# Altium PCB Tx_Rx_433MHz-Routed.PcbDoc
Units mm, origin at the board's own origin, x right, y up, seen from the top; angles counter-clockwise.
Board outline 100 x 100 mm, 4 copper layers (SIGNAL_1, SIGNAL_2, SIGNAL_3, SIGNAL_4), stack 1.58 mm thick; 85 components, 84 nets, 318 pads, 423 vias.
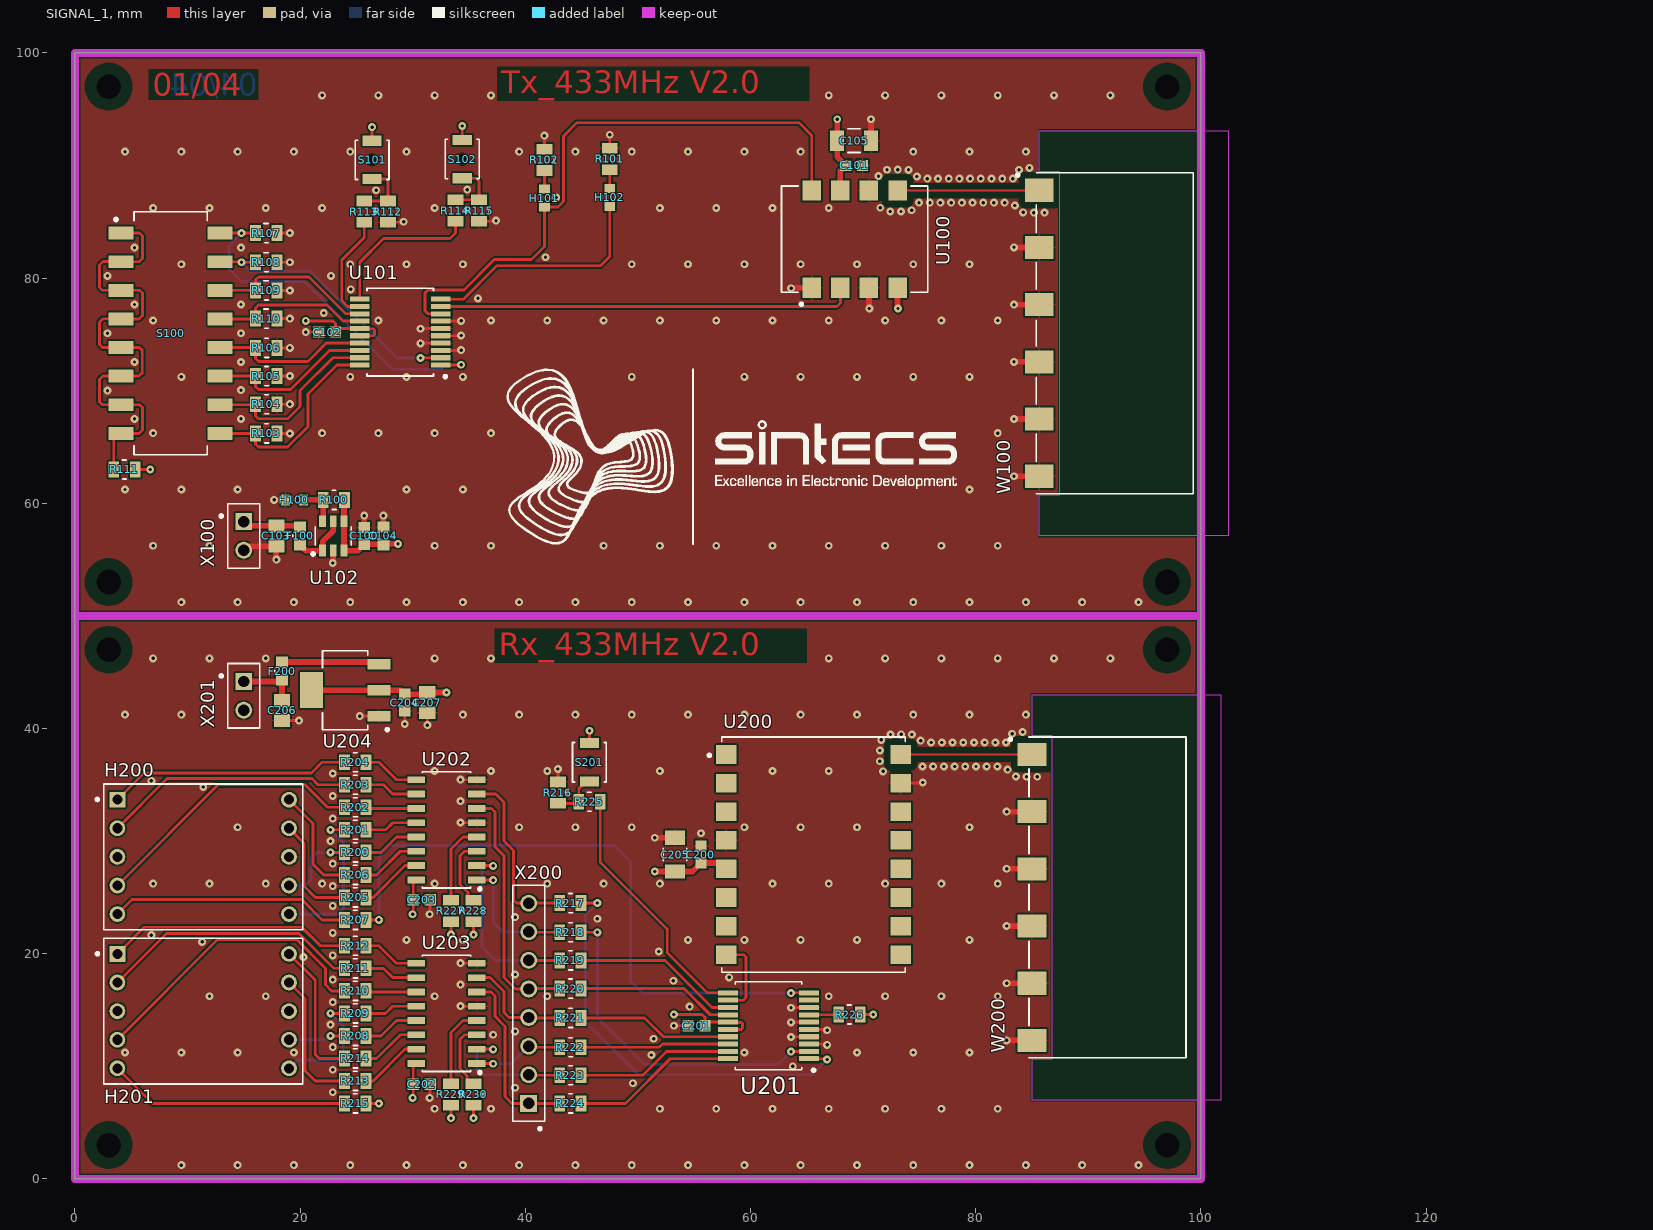
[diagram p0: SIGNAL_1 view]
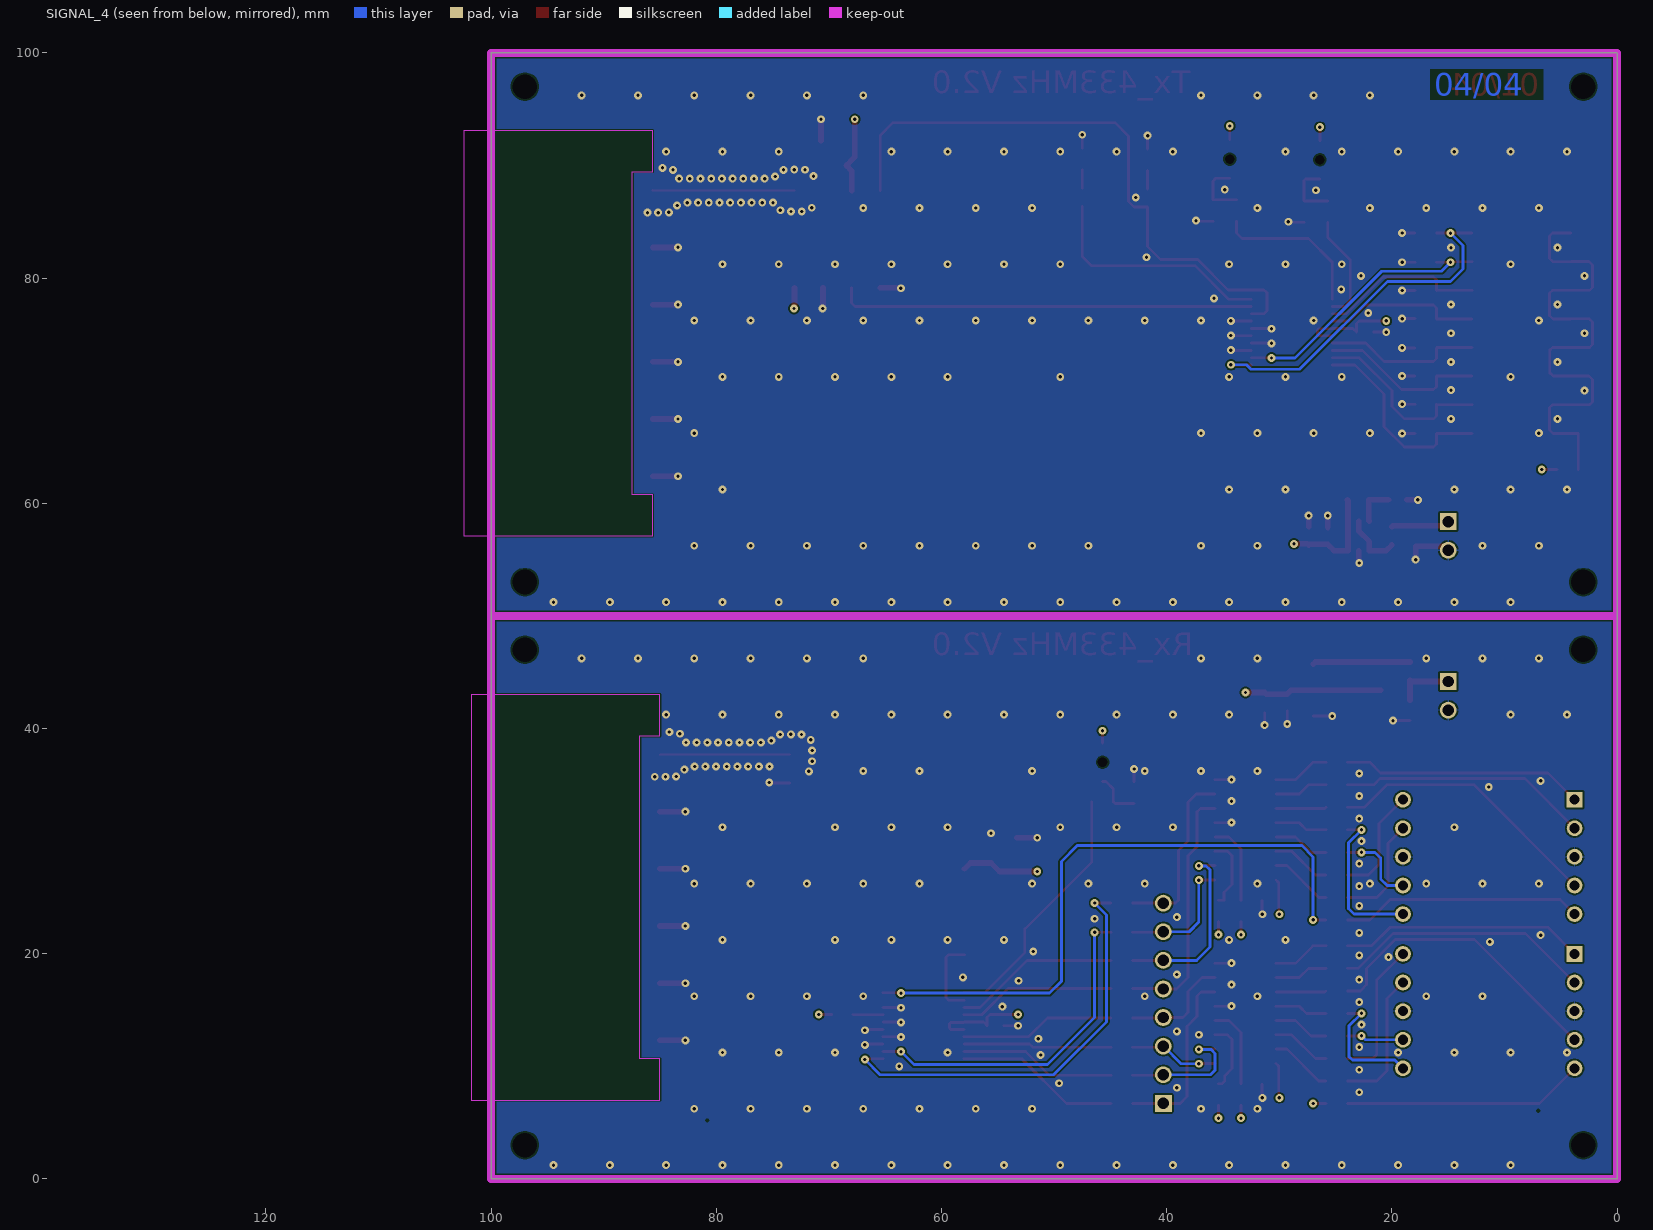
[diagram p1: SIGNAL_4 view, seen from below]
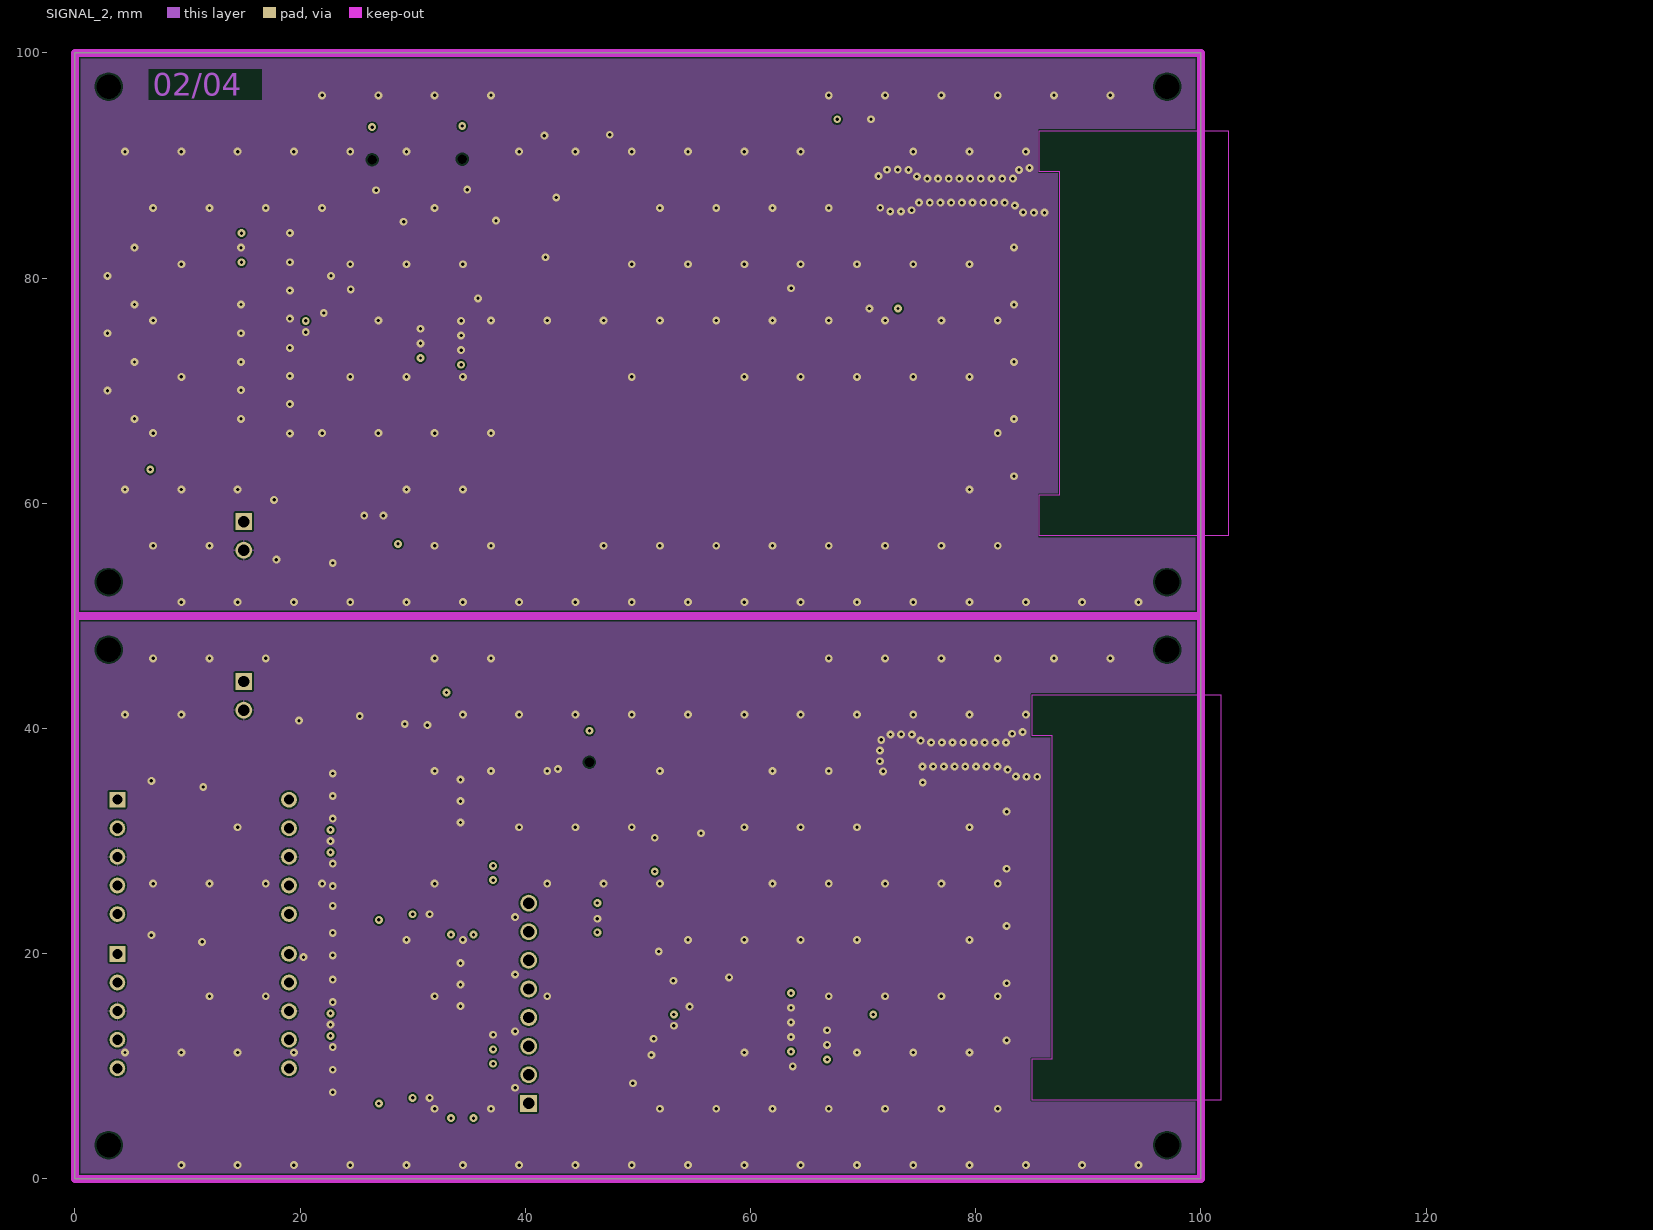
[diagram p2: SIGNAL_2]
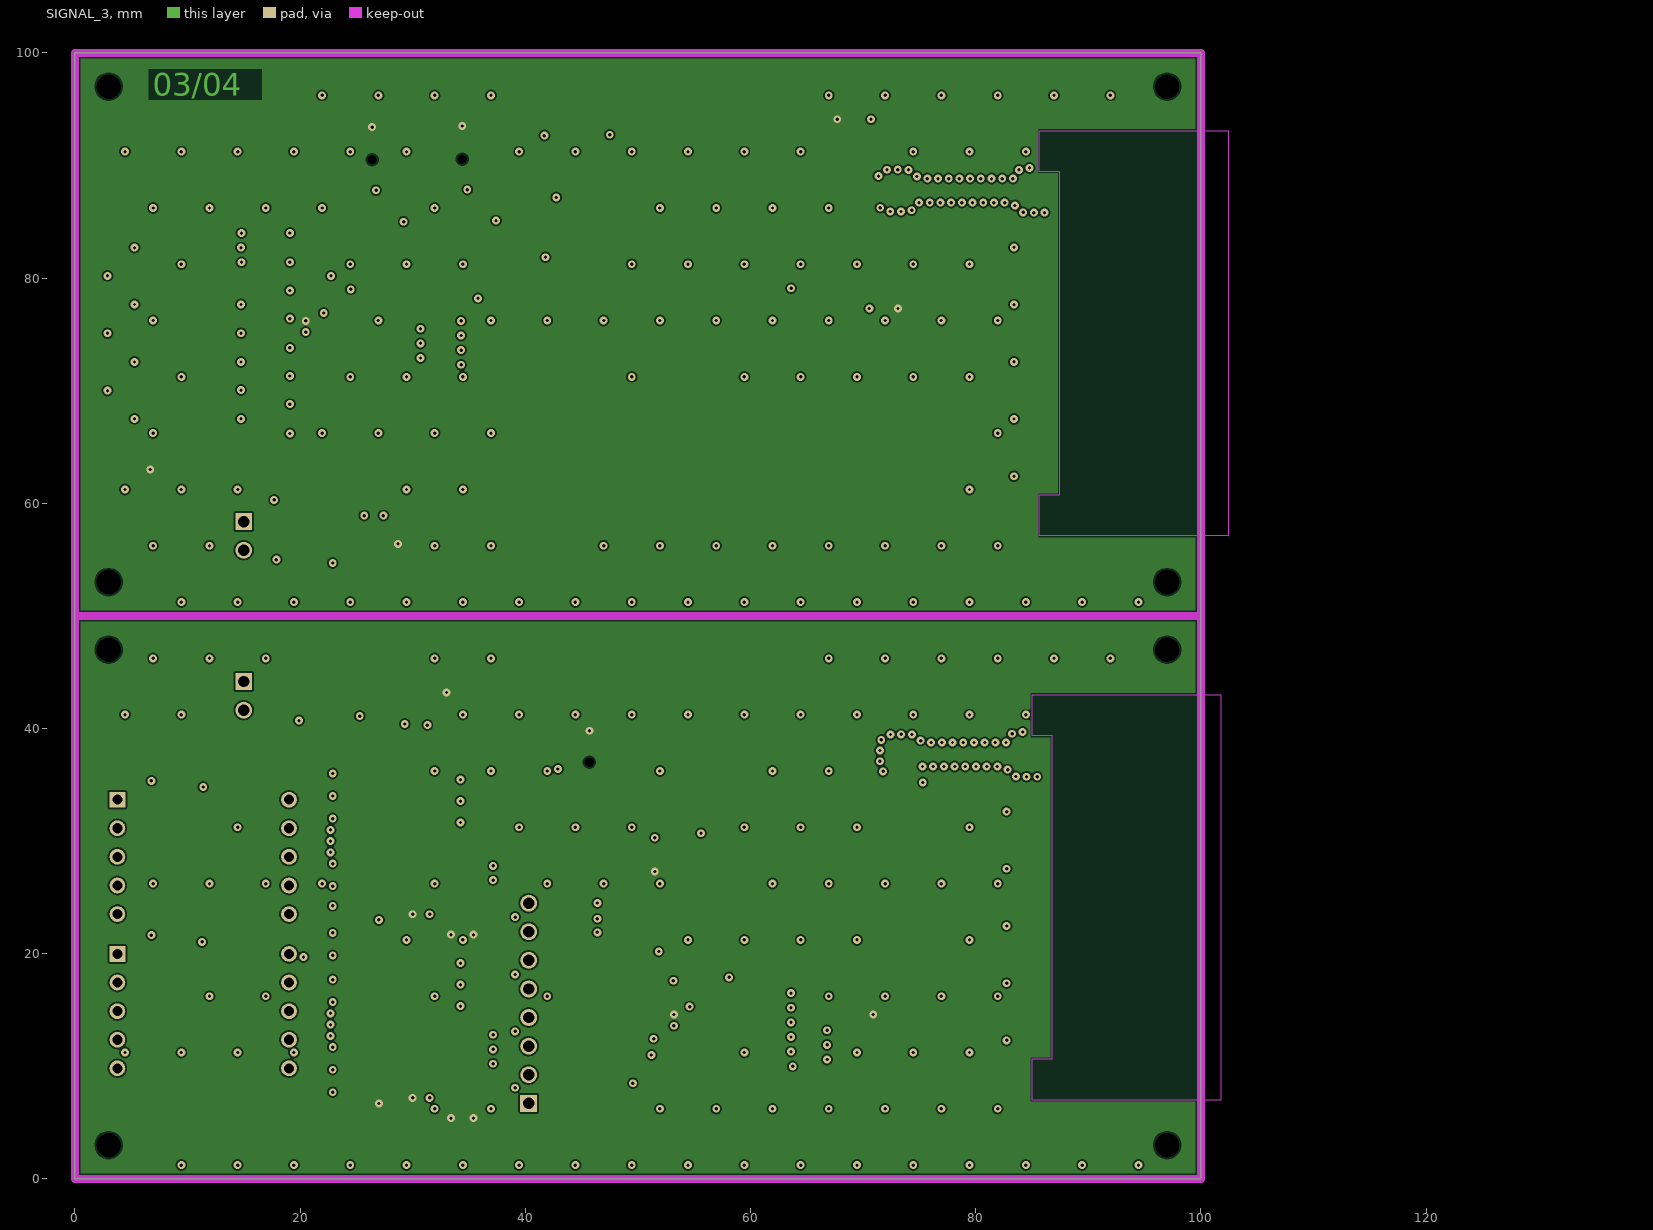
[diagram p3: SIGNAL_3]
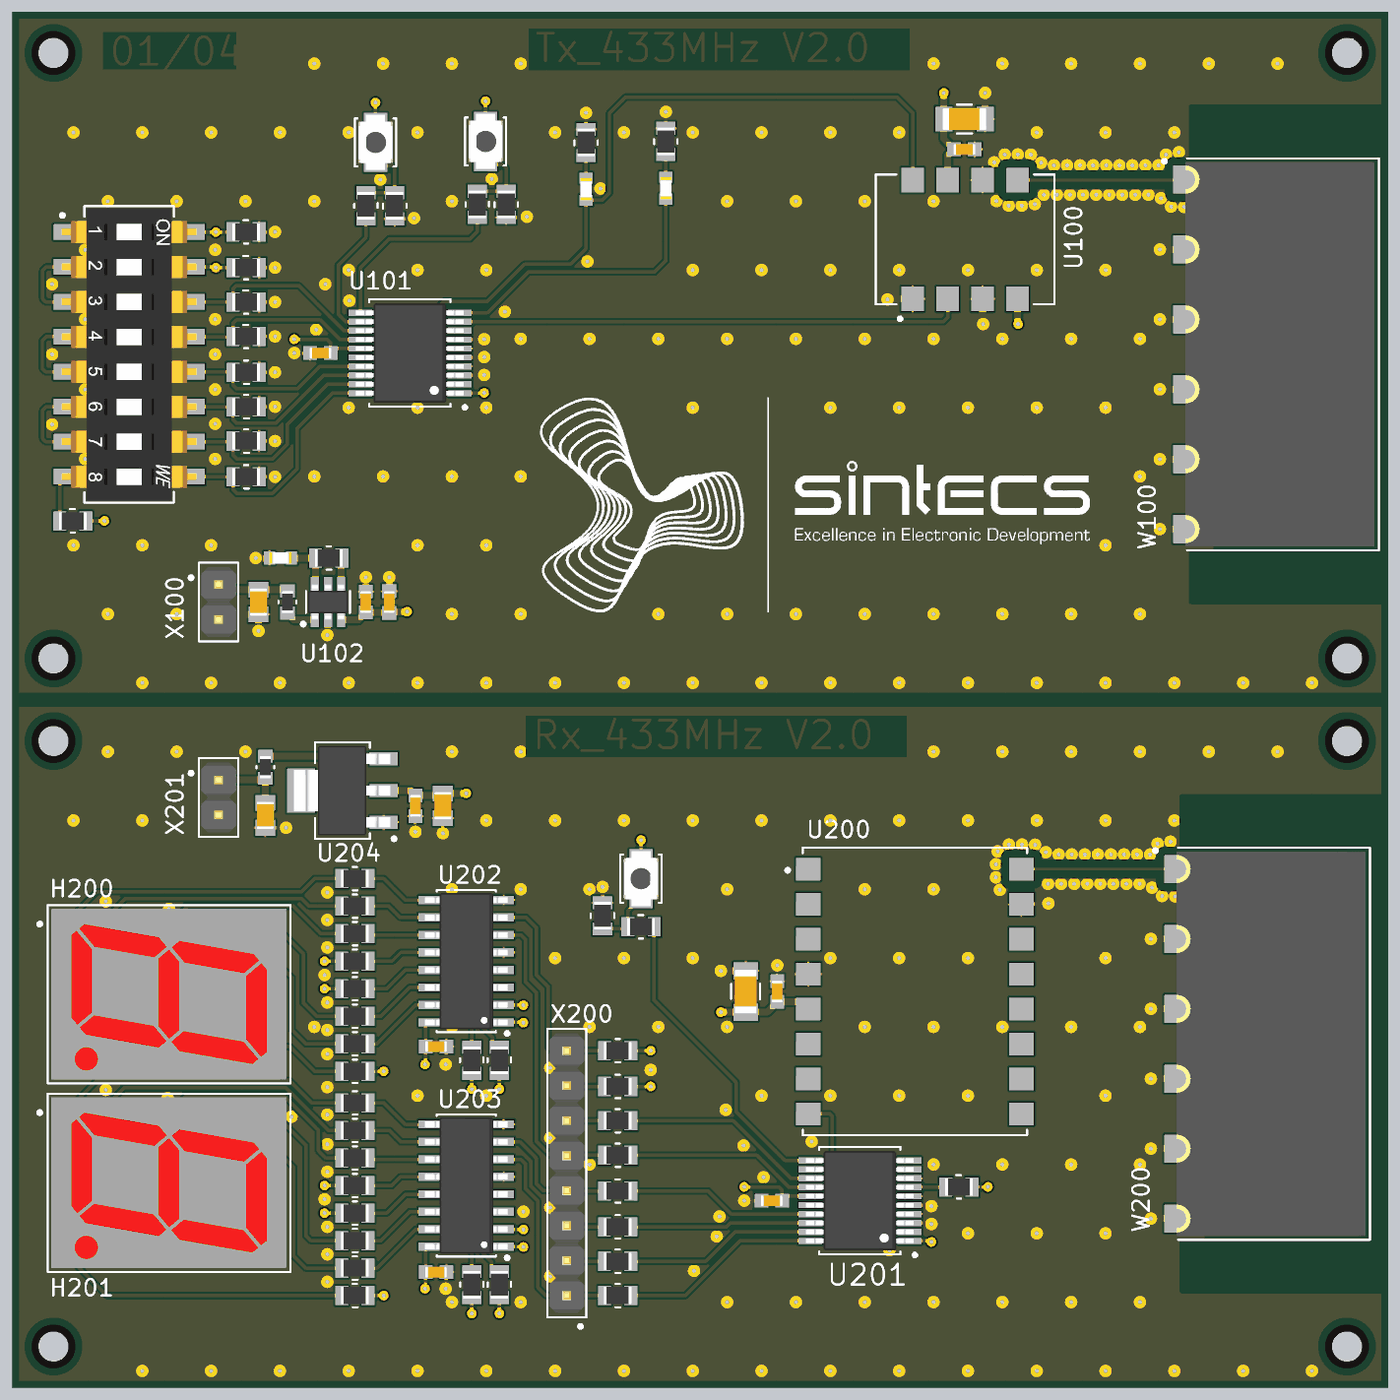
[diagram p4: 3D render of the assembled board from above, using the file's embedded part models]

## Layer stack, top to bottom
DIELECTRIC_1: solder mask 0.01, Dk 1
SIGNAL_1: signal copper 0.035
DIELECTRIC_3: prepreg 0.12, Dk 4.7
SIGNAL_2: signal copper 0.035
DIELECTRIC_5: prepreg 1.2, Dk 4.7
SIGNAL_3: signal copper 0.035
DIELECTRIC_7: prepreg 0.12, Dk 4.7
SIGNAL_4: signal copper 0.035
DIELECTRIC_9: solder mask 0.01, Dk 1

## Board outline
0,0 100,0 100,100 0,100

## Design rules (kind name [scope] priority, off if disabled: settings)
Clearance Clearance_50R [InNetClass('50R') vs Not Keepout] p1: gap=0.6 ignorepadtopadclearanceinfootprint=FALSE except(0.2: SMDPad-SMDPad)
Clearance [All] p2: gap=0.15 ignorepadtopadclearanceinfootprint=FALSE
ComponentClearance [All] p1: gap=0.1 collisioncheckmode=3 verticalgap=0.254 showdistances=FALSE
DiffPairsRouting [All] p1: maxlimit=0.254 minlimit=0.254 mostfreqgap=0.254 toplayer_minwidth=0.15 toplayer_maxwidth=0.3 toplayer_prefwidth=0.15 midlayer1_minwidth=0.15 midlayer1_maxwidth=0.3 midlayer1_prefwidth=0.15 midlayer2_minwidth=0.15 midlayer2_maxwidth=0.3 midlayer2_prefwidth=0.15 bottomlayer_minwidth=0.15 bottomlayer_maxwidth=0.3 bottomlayer_prefwidth=0.15 maxuncoupledlength=12.7
MinimumSolderMaskSliver [All] p1: minsoldermaskwidth=0.1
PolygonConnect [All] p1: thpad.connectstyle=Relief thpad.reliefconductorwidth=0.15 thpad.reliefentries=4 thpad.polygonreliefangle="90 Angle" thpad.airgapwidth=0.15 smdpad.connectstyle=Relief smdpad.reliefconductorwidth=0.15 smdpad.reliefentries=4 smdpad.polygonreliefangle="90 Angle" smdpad.airgapwidth=0.15 via.connectstyle=Direct via.reliefconductorwidth=0.127 via.reliefentries=2 via.polygonreliefangle="90 Angle" via.airgapwidth=0.152
RoutingVias [All] p1: holewidth=0.3 width=0.7 viastyle="Through Hole" minholewidth=0.3 minwidth=0.7 maxholewidth=0.3 maxwidth=0.7
SilkToSilkClearance [All] p1: silktosilkclearance=0.1
SolderMaskExpansion SolderMaskExpansion_Via [IsVia] p1: expansion=0.075 istentingtop=FALSE soldermaskfromhole=TRUE
SolderMaskExpansion [All] p2: expansion=0.1 istentingtop=FALSE
UnRoutedNet [All] p1: checkbadconnections=TRUE
Width "Width for 50E_SE" [InNetClass('50R')] p1: maxlimit=0.2 minlimit=0.185 preferedwidth=0.2 toplayer_minwidth=0.2 bottomlayer_minwidth=0.2 impedanceprofiledriven=TRUE impedanceprofileid={877E34D1-77DC-4DEE-A0FB-207FE4FBDA97} impedanceprofilevalue=50.000000 minimp=50.000000 maximp=50.000000 favimp=50.000000
Width [All] p2: maxlimit=1 minlimit=0.15 preferedwidth=0.2
25 further rules are at their usual default settings.

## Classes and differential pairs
net class 50R: RF_RX RF_TX
component class TX: C100 C101 C102 C103 C104 C105 F100 H100 H101 H102 R100 R101 R102 R103 R104 R105 R106 R107 R108 R109 R110 R111 R112 R113 R114 R115 S100 S101 S102 U100 U101 U102 W100 X100
component class RX: C200 C201 C202 C203 C204 C205 C206 C207 F200 H200 H201 R200 R201 R202 R203 R204 R205 R206 R207 R208 R209 R210 R211 R212 R213 R214 R215 R216 R217 R218 R219 R220 R221 R222 R223 R224 R225 R226 R227 R228 R229 R230 S201 U200 U201 U202 U203 U204 W200 X200 X201
polygon class "\"(Inherited)\"": GND_RX_L02_P002

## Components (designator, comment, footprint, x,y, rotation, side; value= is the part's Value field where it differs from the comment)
C100 "C_0603_1608X90_GENERIC" CAPC1608X90N_0603_GENERIC 25.7,57.1 r90 top value=100nF
C101 "C_0603_1608X90_GENERIC" CAPC1608X90N_0603_GENERIC 69.2,90 r0 top value=100nF
C102 "C_0603_1608X90_GENERIC" CAPC1608X90N_0603_GENERIC 22.4,75.2 r180 top value=100nF
C103 "C_0805_2012X150_GENERIC" CAPC2012X150N_0805_GENERIC 17.9,57.1 r270 top value=1uF
C104 "CL10A226MP8NUNE" CAPC1608X105N 27.4,57.1 r90 top value=4.7uF
C105 "C_1206_3216X190_GENERIC" CAPC3216X190N_1206_GENERIC 69.2,92.2 r0 top value=10uF
C200 "C_0603_1608X90_GENERIC" CAPC1608X90N_0603_GENERIC 55.6,28.8 r90 top value=100nF
C201 "C_0603_1608X90_GENERIC" CAPC1608X90N_0603_GENERIC 55.2,13.6 r180 top value=100nF
C202 "C_0603_1608X90_GENERIC" CAPC1608X90N_0603_GENERIC 30.8,8.4 r0 top value=100nF
C203 "C_0603_1608X90_GENERIC" CAPC1608X90N_0603_GENERIC 30.8,24.8 r0 top value=100nF
C204 "C_0603_1608X90_GENERIC" CAPC1608X90N_0603_GENERIC 29.3,42.3 r270 top value=100nF
C205 "C_1206_3216X190_GENERIC" CAPC3216X190N_1206_GENERIC 53.3,28.8 r90 top value=10uF
C206 "08051C104KAZ2A" CAPC2013X140N_AVX 18.398,41.6 r270 top value=10uF
C207 "08051C104KAZ2A" CAPC2013X140N_AVX 31.3,42.3 r270 top value=10uF
F100 "0467XXXX" RESC1608X60N_0603_GENERIC 20,57.1 r270 top value=500mA
F200 "0467XXXX" RESC1608X60N_0603_GENERIC 18.4,45.1 r90 top value=500mA
H100 "KP-1608SGC" LEDC1608X110N 19.5,60.3 r180 top
H101 "KP-1608SGC" LEDC1608X110N 41.7,87.1 r90 top
H102 "KP-1608SGC" LEDC1608X110N 47.5,87.175 r90 top
H200 "HDSP-5XXX" BROADCOM_HDSP-5XXX 11.4,28.6 r0 top
H201 "HDSP-5XXX" BROADCOM_HDSP-5XXX 11.4,14.9 r0 top
R100 "R_0805_2012X60_GENERIC" RESC2012X60N_0805_GENERIC 23,60.3 r180 top value=120R
R101 "R_0805_2012X60_GENERIC" RESC2012X60N_0805_GENERIC 47.5,90.575 r90 top value=120R
R102 "R_0805_2012X60_GENERIC" RESC2012X60N_0805_GENERIC 41.7,90.5 r90 top value=120R
R103 "R_0805_2012X60_GENERIC" RESC2012X60N_0805_GENERIC 17,66.2 r180 top value=100K
R104 "R_0805_2012X60_GENERIC" RESC2012X60N_0805_GENERIC 17,68.8 r180 top value=100K
R105 "R_0805_2012X60_GENERIC" RESC2012X60N_0805_GENERIC 17,71.3 r180 top value=100K
R106 "R_0805_2012X60_GENERIC" RESC2012X60N_0805_GENERIC 17,73.8 r180 top value=100K
R107 "R_0805_2012X60_GENERIC" RESC2012X60N_0805_GENERIC 17,84 r0 top value=100K
R108 "R_0805_2012X60_GENERIC" RESC2012X60N_0805_GENERIC 17,81.4 r0 top value=100K
R109 "R_0805_2012X60_GENERIC" RESC2012X60N_0805_GENERIC 17,78.9 r0 top value=100K
R110 "R_0805_2012X60_GENERIC" RESC2012X60N_0805_GENERIC 17,76.4 r0 top value=100K
R111 "R_0805_2012X60_GENERIC" RESC2012X60N_0805_GENERIC 4.4,63 r0 top value=1K
R112 "R_0805_2012X60_GENERIC" RESC2012X60N_0805_GENERIC 27.8,85.9 r90 top value=100K
R113 "R_0805_2012X60_GENERIC" RESC2012X60N_0805_GENERIC 25.7,85.9 r270 top value=1K
R114 "R_0805_2012X60_GENERIC" RESC2012X60N_0805_GENERIC 33.8,86 r270 top value=1K
R115 "R_0805_2012X60_GENERIC" RESC2012X60N_0805_GENERIC 35.9,86 r90 top value=100K
R200 "R_0805_2012X60_GENERIC" RESC2012X60N_0805_GENERIC 24.9,29.001 r180 top value=120R
R201 "R_0805_2012X60_GENERIC" RESC2012X60N_0805_GENERIC 24.9,31.001 r180 top value=120R
R202 "R_0805_2012X60_GENERIC" RESC2012X60N_0805_GENERIC 24.9,33.001 r180 top value=120R
R203 "R_0805_2012X60_GENERIC" RESC2012X60N_0805_GENERIC 24.9,35.001 r180 top value=120R
R204 "R_0805_2012X60_GENERIC" RESC2012X60N_0805_GENERIC 24.9,37.002 r180 top value=120R
R205 "R_0805_2012X60_GENERIC" RESC2012X60N_0805_GENERIC 24.9,25 r180 top value=120R
R206 "R_0805_2012X60_GENERIC" RESC2012X60N_0805_GENERIC 24.9,27 r180 top value=120R
R207 "R_0805_2012X60_GENERIC" RESC2012X60N_0805_GENERIC 24.9,23 r180 top value=120R
R208 "R_0805_2012X60_GENERIC" RESC2012X60N_0805_GENERIC 24.9,12.7 r180 top value=120R
R209 "R_0805_2012X60_GENERIC" RESC2012X60N_0805_GENERIC 24.9,14.7 r180 top value=120R
R210 "R_0805_2012X60_GENERIC" RESC2012X60N_0805_GENERIC 24.9,16.701 r180 top value=120R
R211 "R_0805_2012X60_GENERIC" RESC2012X60N_0805_GENERIC 24.9,18.701 r180 top value=120R
R212 "R_0805_2012X60_GENERIC" RESC2012X60N_0805_GENERIC 24.9,20.701 r180 top value=120R
R213 "R_0805_2012X60_GENERIC" RESC2012X60N_0805_GENERIC 24.9,8.7 r180 top value=120R
R214 "R_0805_2012X60_GENERIC" RESC2012X60N_0805_GENERIC 24.9,10.7 r180 top value=120R
R215 "R_0805_2012X60_GENERIC" RESC2012X60N_0805_GENERIC 24.9,6.7 r180 top value=120R
R216 "R_0805_2012X60_GENERIC" RESC2012X60N_0805_GENERIC 42.9,34.3 r270 top value=100K
R217 "R_0805_2012X60_GENERIC" RESC2012X60N_0805_GENERIC 44,24.5 r180 top value=1K
R218 "R_0805_2012X60_GENERIC" RESC2012X60N_0805_GENERIC 44,21.9 r180 top value=1K
R219 "R_0805_2012X60_GENERIC" RESC2012X60N_0805_GENERIC 44,19.4 r180 top value=1K
R220 "R_0805_2012X60_GENERIC" RESC2012X60N_0805_GENERIC 44,16.9 r180 top value=1K
R221 "R_0805_2012X60_GENERIC" RESC2012X60N_0805_GENERIC 44,14.3 r180 top value=1K
R222 "R_0805_2012X60_GENERIC" RESC2012X60N_0805_GENERIC 44,11.7 r180 top value=1K
R223 "R_0805_2012X60_GENERIC" RESC2012X60N_0805_GENERIC 44,9.2 r180 top value=1K
R224 "R_0805_2012X60_GENERIC" RESC2012X60N_0805_GENERIC 44,6.7 r180 top value=1K
R225 "R_0805_2012X60_GENERIC" RESC2012X60N_0805_GENERIC 45.7,33.5 r0 top value=1K
R226 "R_0805_2012X60_GENERIC" RESC2012X60N_0805_GENERIC 68.8,14.6 r0 top value=100K
R227 "R_0805_2012X60_GENERIC" RESC2012X60N_0805_GENERIC 33.4,23.8 r270 top value=100K
R228 "R_0805_2012X60_GENERIC" RESC2012X60N_0805_GENERIC 35.4,23.8 r270 top value=100K
R229 "R_0805_2012X60_GENERIC" RESC2012X60N_0805_GENERIC 33.4,7.5 r270 top value=100K
R230 "R_0805_2012X60_GENERIC" RESC2012X60N_0805_GENERIC 35.4,7.5 r270 top value=100K
S100 "418121270808" WE_418121270808 8.5,75.1 r0 top
S101 "B3U_1000P_B" OMRON_B3U_1000P_B 26.4,90.5 r90 top
S102 "B3U_1000P_B" OMRON_B3U_1000P_B 34.402,90.57 r90 top
S201 "B3U_1000P_B" OMRON_B3U_1000P_B 45.7,37 r270 top
U100 "TXM-433-LR" LINX_TXM-433-LR 69.25,83.45 r90 top
U101 "LICAL-ENC-MS001" SOP65P780X200-20N 28.9,75.2 r180 top
U102 "MAX8881EU" SOT95P280X100-6N 22.95,57.1 r90 top
U200 "RXM-433-LR" LINX_RXM-433-LR 65.6,28.8 r0 top
U201 "LICAL-DEC-MS001" SOP65P780X200-20N 61.6,13.6 r180 top
U202 "CD74HC4511M" SOIC127P600X175-16N 33,31 r180 top
U203 "CD74HC4511M" SOIC127P600X175-16N 33,14.7 r180 top
U204 "LM1117MPX" SOT230P700X180-4N 25.498,43.4 r180 top
W100 "ANT-433-SP" LINX_ANT-433-SP 85.65,75.1 r270 top
W200 "ANT-433-SP" LINX_ANT-433-SP 85,25 r270 top
X100 "M20_9770242" HARWIN_M20_9770242 15,57.1 r270 top
X200 "M20_9770842" HARWIN_M20_9770842 40.3,15.6 r90 top
X201 "M20_9770242" HARWIN_M20_9770242 15,42.9 r270 top

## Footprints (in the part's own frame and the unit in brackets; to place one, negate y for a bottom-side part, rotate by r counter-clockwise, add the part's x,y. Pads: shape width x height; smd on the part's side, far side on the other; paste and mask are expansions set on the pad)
BROADCOM_HDSP-5XXX [mm]
  rrect1% 1.4x1.4 hole 0.9 paste-2539.97 mask-0.713: 1(-7.62,5.08)
  round 1.4 hole 0.9 paste-2539.97 mask-0.713: 2(-7.62,2.54) 3(-7.62,0) 4(-7.62,-2.54) 5(-7.62,-5.08) 6(7.62,-5.08) 7(7.62,-2.54) 8(7.62,0) 9(7.62,2.54) 10(7.62,5.08)
  silkscreen extent -9.53,-6.47 8.83,6.48, body extent -8.55,-6.2 8.55,6.2, height 8
CAPC1608X90N_0603_GENERIC [mm]
  rrect1% 1x1 smd paste+0 mask-0.513: 1(-0.75,0) 2(0.75,0)
  body extent -0.8,-0.4 0.8,0.4, height 0.8
CAPC1608X105N [mm]
  rrect1% 1x1.05 smd paste+0 mask-0.538: 1(-0.8,0) 2(0.8,0)
  body extent -0.8,-0.4 0.8,0.4, height 0.8
CAPC2012X150N_0805_GENERIC [mm]
  rrect1% 1.15x1.45 smd paste+0 mask-0.738: 1(-0.9,0) 2(0.9,0)
  body extent -1,-0.63 1,0.63, height 1
CAPC2013X140N_AVX [mm]
  rrect1% 1.15x1.45 smd paste+0 mask-0.738: 1(-0.9,0) 2(0.9,0)
  body extent -1,-0.63 1,0.63, height 1
CAPC3216X190N_1206_GENERIC [mm]
  rrect1% 1.25x1.8 smd paste+0 mask-0.913: 1(-1.5,0) 2(1.5,0)
  silkscreen extent -0.55,-1.05 0.55,1.05, body extent -1.6,-0.8 1.6,0.8, height 1.2
HARWIN_M20_9770242 [mm]
  rrect1% 1.5x1.5 hole 1 paste-2539.97 mask-0.763: 1(-1.27,0)
  round 1.5 hole 1 paste-2539.97 mask-0.763: 2(1.27,0)
  silkscreen extent -2.87,-2.13 2.86,1.42, body extent -2.54,-1.27 2.54,1.27, height 8.34
HARWIN_M20_9770842 [mm]
  rrect1% 1.5x1.5 hole 1 paste-2539.97 mask-0.763: 1(-8.89,0)
  round 1.5 hole 1 paste-2539.97 mask-0.763: 2(-6.35,0) 3(-3.81,0) 4(-1.27,0) 5(1.27,0) 6(3.81,0) 7(6.35,0) 8(8.89,0)
  silkscreen extent -11.26,-1.42 10.48,1.42, body extent -10.16,-1.27 10.16,1.27, height 8.34
LEDC1608X110N [mm]
  rrect1% 0.8x0.95 smd paste+0 mask-0.488: 1(-0.8,0) 2(0.8,0)
  body extent -0.8,-0.4 0.81,0.4, height 0.75
LINX_ANT-433-SP [mm]
  rrect1% 2.05x2.55 smd paste+0 mask-1.288: 1(-12.7,0) 2(-7.62,0) 3(-2.54,0) 4(2.54,0) 5(7.62,0) 6(12.7,0)
  Keep-Out Layer region: 14.35,0 14.35,1.8 -14.35,1.8 -14.35,0 -18,0 -18,16.78 18,16.78 18,0
  silkscreen extent -14.24,-2.04 14.24,13.67, body extent -13.97,-0.38 13.97,13.34, height 1.52
LINX_RXM-433-LR [mm]
  rrect1% 1.8x1.65 smd paste+0 mask-0.913: 1(-7.747,8.89) 2(-7.747,6.35) 3(-7.747,3.81) 4(-7.747,1.27) 5(-7.747,-1.27) 6(-7.747,-3.81) 7(-7.747,-6.35) 8(-7.747,-8.89) 9(7.747,-8.89) 10(7.747,-6.35) 11(7.747,-3.81) 12(7.747,-1.27) 13(7.747,1.27) 14(7.747,3.81) 15(7.747,6.35) 16(7.747,8.89)
  silkscreen extent -9.38,-10.45 8.15,10.45, body extent -8,-10.3 8,10.4, height 3.3
LINX_TXM-433-LR [mm]
  rrect1% 1.8x1.65 smd paste+0 mask-0.913: 1(-4.318,3.81) 2(-4.318,1.27) 3(-4.318,-1.27) 4(-4.318,-3.81) 5(4.318,-3.81) 6(4.318,-1.27) 7(4.318,1.27) 8(4.318,3.81)
  silkscreen extent -5.89,-6.5 4.72,6.5, body extent -4.6,-6.4 4.6,6.4, height 3.3
OMRON_B3U_1000P_B [mm]
  rrect1% 0.9x1.7 smd paste+0 mask-0.863: 1(-1.7,0) 2(1.7,0)
  round 0 hole 0.85 unplated paste-2539.97: ""(0,0)
  silkscreen extent -1.75,-1.5 1.75,1.5, body extent -2,-1.25 2,1.25, height 1.75
RESC1608X60N_0603_GENERIC [mm]
  rrect1% 0.95x1.05 smd paste+0 mask-0.538: 1(-0.8,0) 2(0.8,0)
  silkscreen extent -0.08,-0.65 0.08,0.65, body extent -0.8,-0.4 0.8,0.4, height 0.5
RESC2012X60N_0805_GENERIC [mm]
  rrect1% 0.95x1.4 smd paste+0 mask-0.713: 1(-0.95,0) 2(0.95,0)
  silkscreen extent -0.2,-0.85 0.15,0.85, body extent -1,-0.63 1,0.63, height 0.5
SOIC127P600X175-16N [mm]
  rrect1% 1.55x0.6 smd paste+0 mask-0.788: 1(-2.7,4.445) 2(-2.7,3.175) 3(-2.7,1.905) 4(-2.7,0.635) 5(-2.7,-0.635) 6(-2.7,-1.905) 7(-2.7,-3.175) 8(-2.7,-4.445) 9(2.7,-4.445) 10(2.7,-3.175) 11(2.7,-1.905) 12(2.7,-0.635) 13(2.7,0.635) 14(2.7,1.905) 15(2.7,3.175) 16(2.7,4.445)
  silkscreen extent -3.1,-5.16 2.15,5.38, body extent -3,-4.95 3,4.95, height 1.75
SOP65P780X200-20N [mm]
  rrect1% 1.75x0.45 smd paste+0 mask-0.888: 1(-3.6,2.925) 2(-3.6,2.275) 3(-3.6,1.625) 4(-3.6,0.975) 5(-3.6,0.325) 6(-3.6,-0.325) 7(-3.6,-0.975) 8(-3.6,-1.625) 9(-3.6,-2.275) 10(-3.6,-2.925) 11(3.6,-2.925) 12(3.6,-2.275) 13(3.6,-1.625) 14(3.6,-0.975) 15(3.6,-0.325) 16(3.6,0.325) 17(3.6,0.975) 18(3.6,1.625) 19(3.6,2.275) 20(3.6,2.925)
  silkscreen extent -4.13,-3.9 2.95,4.08, body extent -3.93,-3.6 3.93,3.6, height 2
SOT95P280X100-6N [mm]
  rrect1% 1.05x0.6 smd paste+0 mask-0.538: 1(-1.3,0.95) 2(-1.3,0) 3(-1.3,-0.95) 4(1.3,-0.95) 5(1.3,0) 6(1.3,0.95)
  silkscreen extent -1.73,-1.6 0.8,1.92, body extent -1.28,-1.45 1.28,1.45, height 1.45
SOT230P700X180-4N [mm]
  rrect1% 2.05x0.95 smd paste+0 mask-1.038: 1(-1.5,2.3) 2(-1.5,0) 3(-1.5,-2.3)
  rrect1% 2.05x3.2 smd paste+0 mask-1.613: 4(4.5,0)
  silkscreen extent -2.37,-3.5 3.5,3.63, body extent -1.98,-3.25 5.02,3.25, height 1.8
WE_418121270808 [mm]
  rrect1% 2.2x1.15 smd paste+0 mask-1.113: 1(-4.4,8.89) 2(-4.4,6.35) 3(-4.4,3.81) 4(-4.4,1.27) 5(-4.4,-1.27) 6(-4.4,-3.81) 7(-4.4,-6.35) 8(-4.4,-8.89) 9(4.4,-8.89) 10(4.4,-6.35) 11(4.4,-3.81) 12(4.4,-1.27) 13(4.4,1.27) 14(4.4,3.81) 15(4.4,6.35) 16(4.4,8.89)
  silkscreen extent -4.97,-10.78 3.25,10.78, body extent -4.9,-10.63 4.9,10.63, height 4.32

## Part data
C100 C101 C102 C200 C201 C202 C203 C204: "100nF 25V 10%", Capacitance=100000, Dielectric=X7R, Manufacturer=MURATA, MPN=GRM188R71E104KA01D, Package=0603, Part Name="Ceramic chip capacitor 0603-1608x90, generic", Tolerance=10, Voltage=25V
C103: "1µF 25V 10%", Capacitance=1000000, Dielectric=X7R, Manufacturer=AVX, MPN=08053C105K4Z2A, Package=0805, Part Name="Ceramic chip capacitor 0805-2012x150, generic", Tolerance=10, Voltage=25V
C104: "4.7uF 25V 10%", Alternate Manufacturer=SAMSUNG, Alternate MPN=CL10A475KA8NQNC, Capacitance=4700000, Dielectric=X5R, Manufacturer=AVX, MPN=06033D475KAT2A, Package=0603, Part Name="CAP 22uF 10V 0603 X5R", Tolerance=10, Voltage=25V
C105 C205: "10uF 25V 10%", Capacitance=10000000, Dielectric=X7R, Manufacturer=AVX, Max Temp=+125, Min Temp=-55, MPN=12063C106KAT2A, Package=1206, Part Name="Cheramic chip capacitor 1206-3216x190, generic", Tolerance=10, Voltage=25V
C206 C207: "10uF 25V 10%", Capacitance=10000000, Dielectric=X5R, Manufacturer=AVX, MPN=08053D106KAT2A, Package=0805, Part Name="0805 chip 100nF 10% 100V X7R", Tolerance=10, Voltage=25V
F100 F200: "Thin film 0603 fuse very fast acting", Current=0.5, Manufacturer=LITTELFUSE, Max Temp=+90, Min Temp=-55, MPN=0467.500NRHF, Package=0603, Part Name="Thin film 0603 very fast acting", Voltage=32V
H100 H101 H102: "LED Green", Current=20mA, Manufacturer=KINGBRIGHT, MPN=APT-1608SGC, Package=0603, Part Name="SMD LED lamp, Green"
H200 H201: "7 Segment Display Module Red, 1,85V, 20mA. THT", Color=Red, Manufacturer=BROADCOM, Max Temp=85, Min Temp=-25, MPN=HDSP-515A, Part Name="Single Digit LED Numeric Display, Blue color"
R100 R101 R102 R200 R201 R202 R203 R204 R205 R206 R207 R208 R209 R210 R211 R212 R213 R214 R215: "0.125W 5% 120R 50V", Manufacturer=YAGEO, MPN=RC0805JR-07120RL, Package=0805, Part Name="resistor_0805-2012x60 generic", Tolerance=5%
R103 R104 R105 R106 R107 R108 R109 R110 R112 R115 R216 R226 R227 R228 R229 R230: "0.125W 5% 100K 50V", Manufacturer=YAGEO, MPN=RC0805JR-07100KL, Package=0805, Part Name="resistor_0805-2012x60 generic", Tolerance=5%
R111 R113 R114 R217 R218 R219 R220 R221 R222 R223 R224 R225: "Resistor_1K_1%_0805", Manufacturer=MULTICOMP, MPN=MCPWR05FTEW1001, Package=0805, Part Name="resistor_0805-2012x60 generic", Tolerance=1%
S100: "Dip Switch SPST 8 Position Surface Mount Slide (Standard) Actuator 25mA 24VDC", Current=25mA, Manufacturer="WURTH ELEKTRONIK", Max Temp=85, Min Temp=-40, Part Name="Dip Switch SPST 8 Position Surface Mount", Voltage=24
S101 S102 S201: "Ultra-small Tactile Switch", Manufacturer=OMRON, Max Temp=0, MPN=B3U-1000P-B
U100: "LR Series Transmitter, Low Voltage, Low Power", Manufacturer="Linx Technologies", Max Temp=85, Min Temp=-40, Package=custom
U101: "MS Series Remote Controler Encoder, Low Voltage, Low Power", Manufacturer="LINX TECHNOLOGIES", Max Temp=85, Min Temp=-40, Package=SOP-20
U102: "Low Dropout Linear Regulator with enable and power good, 3.3V, 6 pin SOT23", Manufacturer=MAXIM, Max Temp=85, Min Temp=-40, MPN=MAX8881EUT33+T, Output Current=0.20A, Package=SOT23-6, Part Name="Low Dropout Linear Regulator, 6 pin SOT23"
U200: "LR Series Receiver, Low Voltage, Low Power", Manufacturer="Linx Technologies", Max Temp=70, Min Temp=-40, Package=custom
U201: "MS Series Remote Controler Decoder, Low Voltage, Low Power", Manufacturer="LINX TECHNOLOGIES", Max Temp=85, Min Temp=-40, MPN=LICAL-DEC-MS001-T, Package=SOP-20
U202 U203: "Leddriver BCD to 7 segment 1 Digit", Manufacturer="TEXAS INSTRUMENTS", Max Temp=125, Min Temp=-55, Package=SOIC-16N
U204: "3.3V/1A fixed regulator", Manufacturer=ON-SEMI, MPN=NCP1117LPST33T3G, Package=SOT, Part Name="800mA Low-Dropout Linear Regulator, SOT223"
W100 W200: "433MHz 50 Ohm Antenna module", Manufacturer="Linx Technologies", Max Temp=130, Min Temp=-40, Package=custom
X100 X201: "1x2 pin 2.54 mm pitch vertical header", Manufacturer=HARWIN, MPN=M20-9770242, Package=header, Part Name=STD_HEADER_1x2_2.54_THT
X200: "1x8 pin 2.54 mm pitch vertical header", Manufacturer=HARWIN, MPN=M20-9770842, Package=header, Part Name=STD_HEADER_1x8_2.54_THT

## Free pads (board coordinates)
  round 0 hole 2.2 unplated paste-2539.97 mask+1.6: ""(3,3) ""(3,47) ""(3,53) ""(3,97) ""(97,3) ""(97,47) ""(97,53) ""(97,97)
  round 0.025 smd far side paste-2539.97 mask-127: ""(7,6.05) ""(80.8,5.2) ""(136.95,83.95)

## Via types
v1: diameter 0.7, hole 0.3, SIGNAL_1 to SIGNAL_4, 423 vias

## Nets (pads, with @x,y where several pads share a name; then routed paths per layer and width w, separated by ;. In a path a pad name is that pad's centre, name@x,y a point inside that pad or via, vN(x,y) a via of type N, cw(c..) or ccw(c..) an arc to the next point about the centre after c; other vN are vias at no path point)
3V3_RX: C200.1 C201.1 C202.1 C203.1 C204.1 C205.1 C207.1 R215.1 R226.2 R227.2 R228.2 R229.2 R230.2 S201.1 U200.5 U201.15 U201.16 U202.16 U203.16 U204.2 U204.4 | length 42.4
  SIGNAL_1 w0.25: R215.1 v1(27,6.7) ; v1(30,7.2) 30.05,7.25 C202.1 30.05,10.005 U203.16 ; v1(30,23.5) 30.05,23.55 30.05,26.305 U202.16 ; v1(33.4,5.4) R229.2 ; v1(33.4,21.7) R227.2 ; v1(35.4,5.4) R230.2 ; v1(35.4,21.7) R228.2 ; S201.1 v1(45.7,39.8) ; v1(53.2,14.6) 55.7,14.6 55.95,14.35 C201.1 56.275,13.925 U201.15 58.025,13.9 59.2,13.9 59.3,13.8 59.3,13.4 59.175,13.275 U201.16 ; R226.2 v1(70.9,14.6)
  SIGNAL_1 w0.5: U204.4 U204.2 28.95,43.4 C204.1 31.15,43.05 C207.1 v1(33,43.2) ; v1(51.5,27.3) C205.1 54.85,27.3 C200.1 57.433,28.05 U200.5@57.953,27.53
3V3_TX: C100.1 C101.1 C102.1 C104.1 C105.1 R100.1 R111.2 S101.2 S102.2 U100.4 U100.7 U101.15 U101.16 U102.3 U102.4 | length 30.9
  SIGNAL_1 w0.25: R111.2 v1(6.7,63) ; v1(20.5,76.2) 22.9,76.2 23.15,75.95 C102.1 23.475,75.525 U101.15 25.325,75.5 26.5,75.5 26.6,75.4 26.6,75 26.475,74.875 U101.16 ; S101.2 v1(26.4,93.4) ; S102.2@34.4,92.3 v1(34.4,93.5)
  SIGNAL_1 w0.5: R100.1 23.9,60.25 U102.4 U102.3 25.15,55.8 C100.1 27.35,56.35 C104.1 27.5,56.4 v1(28.7,56.4) ; v1(67.7,94.1) C105.1 67.7,90.75 C101.1 67.98,89.53 U100.7 ; U100.4 73.06,77.34 v1(73.1,77.3)
DEC_MODE_IND: R207.1 U201.10 | length 57
  SIGNAL_1 w0.25: R207.1 v1(27,23) ; v1(63.6,16.5) 63.625,16.525 U201.10
  SIGNAL_4 w0.25: v1(27,23) 27,28.6 28,29.6 47.95,29.6 49.35,28.2 49.35,17.55 50.4,16.5 v1(63.6,16.5)
GND_RX: C200.2 C201.2 C202.2 C203.2 C204.2 C205.2 C206.2 C207.2 H200.3 H200.8 H201.3 H201.8 R216.1 U200.4 U200.15 U201.3 U201.4 U201.5 U201.6 U201.8 U202.5 U202.8 U203.5 U203.8 U204.1 W200.2 W200.3 W200.4 W200.5 W200.6 X201.2 | length 39.1
  SIGNAL_1 w0.25: C206.2 v1(19.9,40.7) ; v1(25.3,41.1) U204.1 ; v1(29.3,40.4) C204.2 ; v1(31.3,40.3) C207.2 ; v1(31.5,7.2) 31.55,7.25 C202.2 ; v1(31.5,23.5) 31.55,23.55 C203.2@31.55,24.7 ; v1(34.25,15.35) 34.265,15.335 U203.5 ; v1(34.25,19.16) 34.265,19.145 U203.8 ; v1(34.25,31.65) 34.265,31.635 U202.5 ; v1(34.25,35.46) 34.265,35.445 U202.8 ; R216.1 v1(42.9,36.4) ; v1(53.2,13.6) C201.2 ; v1(63.6,12.6) 63.625,12.625 U201.4 ; v1(63.6,13.9) 63.625,13.925 U201.6 ; v1(63.6,15.2) 63.625,15.225 U201.8 ; U201.3 66.725,11.975 v1(66.8,11.9) ; U201.5 66.725,13.275 v1(66.8,13.2) ; U200.15@73.447,35.15 75.25,35.15 v1(75.3,35.2)
  SIGNAL_1 w0.5: v1(51.5,30.3) C205.2 ; v1(82.75,12.3) W200.6 ; v1(82.75,17.38) W200.5 ; v1(82.75,22.46) W200.4 ; v1(82.75,27.54) W200.3 ; v1(82.75,32.62) W200.2
  other v1: 9.454,1.227 14.454,1.227 19.454,1.227 24.454,1.227 29.454,1.227 34.454,1.227 39.454,1.227 44.454,1.227 49.454,1.227 54.454,1.227 59.454,1.227 64.454,1.227 69.454,1.227 74.454,1.227 79.454,1.227 84.454,1.227 89.454,1.227 94.454,1.227 31.954,6.227 36.954,6.227 51.954,6.227 56.954,6.227 61.954,6.227 66.954,6.227 71.954,6.227 76.954,6.227 81.954,6.227 22.9,7.7 39.1,8.1 49.55,8.5 22.9,9.7 63.75,10 51.2,11 4.454,11.227 9.454,11.227 14.454,11.227 19.454,11.227 59.454,11.227 69.454,11.227 74.454,11.227 79.454,11.227 22.9,11.7 51.4,12.45 37.15,12.8 39.1,13.1 22.7,13.7 54.6,15.3 22.9,15.7 11.954,16.227 16.954,16.227 31.954,16.227 41.954,16.227 66.954,16.227 71.954,16.227 76.954,16.227 81.954,16.227 34.25,17.25 53.15,17.6 22.9,17.7 58.1,17.9 39.1,18.15 20.3,19.7 22.9,19.85 51.85,20.2 11.3,21.05 29.454,21.227 34.454,21.227 54.454,21.227 59.454,21.227 64.454,21.227 69.454,21.227 79.454,21.227 6.8,21.65 22.9,21.85 46.4,23.1 39.1,23.25 22.9,24.25 22.9,26 6.954,26.227 11.954,26.227 16.954,26.227 21.954,26.227 31.954,26.227 41.954,26.227 46.954,26.227 51.954,26.227 61.954,26.227 66.954,26.227 71.954,26.227 76.954,26.227 81.954,26.227 22.9,28 22.7,30 55.6,30.7 14.454,31.227 39.454,31.227 44.454,31.227 49.454,31.227 59.454,31.227 64.454,31.227 69.454,31.227 79.454,31.227 22.9,32 34.25,33.55 22.9,34 11.4,34.8 6.8,35.35 84.511,35.716 85.461,35.716 83.561,35.737 22.9,36 71.777,36.188 31.954,36.227 36.954,36.227 41.954,36.227 51.954,36.227 61.954,36.227 66.954,36.227 82.832,36.346 75.273,36.624 76.223,36.624 77.173,36.624 78.123,36.624 79.073,36.624 80.023,36.624 80.973,36.624 81.923,36.624 71.488,37.093 71.488,38.043 76.044,38.756 76.994,38.756 77.944,38.756 78.894,38.756 79.844,38.756 80.794,38.756 81.744,38.756 82.694,38.756 75.108,38.918 71.616,38.985 72.432,39.471 73.382,39.474 74.332,39.466 83.234,39.538 84.172,39.684 4.454,41.227 9.454,41.227 34.454,41.227 39.454,41.227 44.454,41.227 49.454,41.227 54.454,41.227 59.454,41.227 64.454,41.227 69.454,41.227 74.454,41.227 79.454,41.227 84.454,41.227 6.954,46.227 11.954,46.227 16.954,46.227 31.954,46.227 36.954,46.227 66.954,46.227 71.954,46.227 76.954,46.227 81.954,46.227 86.954,46.227 91.954,46.227
GND_TX: C100.2 C101.2 C102.2 C103.2 C104.2 C105.2 H100.2 R101.2 R102.2 R103.1 R104.1 R105.1 R106.1 R107.2 R108.2 R109.2 R110.2 R112.1 R115.1 U100.1 U100.3 U100.6 U101.3 U101.4 U101.5 U101.6 U101.7 U102.2 W100.2 W100.3 W100.4 W100.5 W100.6 X100.2 | length 50
  SIGNAL_1 w0.25: R103.1 v1(19.1,66.2) ; R104.1 v1(19.1,68.8) ; R105.1 v1(19.1,71.3) ; R106.1 v1(19.1,73.8) ; R110.2 v1(19.1,76.4) ; R109.2 v1(19.1,78.9) ; R108.2 v1(19.1,81.4) ; R107.2 v1(19.1,84) ; v1(20.5,75.2) C102.2 ; R112.1 29.15,84.95 v1(29.2,85) ; v1(30.7,74.2) 30.725,74.225 U101.4 ; v1(30.7,75.5) 30.725,75.525 U101.6 ; U101.3 34.275,73.575 v1(34.3,73.6) ; U101.5 34.275,74.875 v1(34.3,74.9) ; U101.7 34.275,76.175 v1(34.3,76.2) ; R115.1 37.35,85.05 v1(37.4,85.1) ; R102.2 v1(41.7,92.65) ; R101.2 v1(47.5,92.725)
  SIGNAL_1 w0.5: X100.2 15.37,56.2 C103.2 v1(17.9,55) ; v1(17.7,60.3) H100.2 ; v1(22.9,54.7) 22.95,54.75 U102.2 ; C100.2 v1(25.7,58.9) ; C104.2 v1(27.4,58.9) ; v1(63.608,79.092) 63.648,79.132 U100.1 ; U100.3 70.52,77.34 v1(70.56,77.3) ; C105.2 v1(70.7,94.1) ; v1(83.4,62.4) W100.6 ; v1(83.4,67.48) W100.5 ; v1(83.4,72.56) W100.4 ; v1(83.4,77.64) W100.3 ; v1(83.4,82.72) W100.2
  other v1: 9.454,51.227 14.454,51.227 19.454,51.227 24.454,51.227 29.454,51.227 34.454,51.227 39.454,51.227 44.454,51.227 49.454,51.227 54.454,51.227 59.454,51.227 64.454,51.227 69.454,51.227 74.454,51.227 79.454,51.227 84.454,51.227 89.454,51.227 94.454,51.227 6.954,56.227 11.954,56.227 31.954,56.227 36.954,56.227 46.954,56.227 51.954,56.227 56.954,56.227 61.954,56.227 66.954,56.227 71.954,56.227 76.954,56.227 81.954,56.227 4.454,61.227 9.454,61.227 14.454,61.227 29.454,61.227 34.454,61.227 79.454,61.227 6.954,66.227 21.954,66.227 26.954,66.227 31.954,66.227 36.954,66.227 81.954,66.227 5.3,67.5 14.75,67.5 2.9,70 14.75,70.05 9.454,71.227 24.454,71.227 29.454,71.227 34.454,71.227 49.454,71.227 59.454,71.227 64.454,71.227 69.454,71.227 74.454,71.227 79.454,71.227 5.3,72.55 14.75,72.55 2.9,75.1 14.75,75.1 6.954,76.227 26.954,76.227 36.954,76.227 41.954,76.227 46.954,76.227 51.954,76.227 56.954,76.227 61.954,76.227 66.954,76.227 71.954,76.227 76.954,76.227 81.954,76.227 22.1,76.9 5.3,77.65 14.75,77.65 35.8,78.2 24.5,79 2.9,80.2 22.75,80.2 9.454,81.227 24.454,81.227 29.454,81.227 34.454,81.227 49.454,81.227 54.454,81.227 59.454,81.227 64.454,81.227 69.454,81.227 74.454,81.227 79.454,81.227 41.8,81.85 5.3,82.7 14.75,82.7 84.211,85.837 85.161,85.816 86.111,85.816 72.414,85.909 73.364,85.909 74.308,86.018 6.954,86.227 11.954,86.227 16.954,86.227 21.954,86.227 31.954,86.227 51.954,86.227 56.954,86.227 61.954,86.227 66.954,86.227 71.523,86.24 83.482,86.446 74.967,86.702 75.917,86.702 76.867,86.702 77.817,86.702 78.767,86.702 79.717,86.702 80.667,86.702 81.617,86.702 82.567,86.702 42.75,87.15 26.75,87.8 34.85,87.85 75.703,88.834 76.653,88.834 77.603,88.834 78.553,88.834 79.503,88.834 80.453,88.834 81.403,88.834 82.353,88.834 83.303,88.834 74.772,89.023 71.363,89.053 72.127,89.619 74.027,89.612 83.847,89.613 73.077,89.627 84.781,89.784 4.454,91.227 9.454,91.227 14.454,91.227 19.454,91.227 24.454,91.227 29.454,91.227 39.454,91.227 44.454,91.227 49.454,91.227 54.454,91.227 59.454,91.227 64.454,91.227 74.454,91.227 79.454,91.227 84.454,91.227 21.954,96.227 26.954,96.227 31.954,96.227 36.954,96.227 66.954,96.227 71.954,96.227 76.954,96.227 81.954,96.227 86.954,96.227 91.954,96.227
NetC103_1: C103.1 F100.1 X100.1 | length 5.2
  SIGNAL_1 w0.5: X100.1 15.37,58 C103.1 19.9,58 F100.1
NetC206_1: C206.1 F200.1 X201.1 | length 5.3
  SIGNAL_1 w0.5: X201.1 18.27,44.17 F200.1 18.4,42.502 C206.1
NetF100_2: F100.2 U102.1 U102.5 | length 5.2
  SIGNAL_1 w0.5: F100.2 20.5,55.8 U102.1 22,56.6 22.95,57.55 U102.5
NetF200_2: F200.2 U204.3 | length 8.7
  SIGNAL_1 w0.5: F200.2 26.798,45.9 U204.3
NetH100_1: H100.1 R100.2 U102.6 | length 3.7
  SIGNAL_1 w0.5: H100.1 R100.2 22.05,58.45 U102.6
NetH101_1: H101.1 U100.8 U101.8 | length 54.5
  SIGNAL_1 w0.25: U101.8 31.375,76.825 31.1,77.1 31.1,78.7 31.35,78.95 34.55,78.95 37.25,81.65 40.55,81.65 41.7,82.8 H101.1 42.9,86.3 43.4,86.8 43.4,92.6 44.6,93.8 64.3,93.8 65.44,92.66 U100.8
NetH101_2: H101.2 R102.1 | length 1.6
  SIGNAL_1 w0.25: H101.2 R102.1
NetH102_1: H102.1 U101.10 | length 21
  SIGNAL_1 w0.25: U101.10 34.525,78.125 37.5,81.1 46.7,81.1 47.5,81.9 H102.1
NetH102_2: H102.2 R101.1 | length 1.6
  SIGNAL_1 w0.25: H102.2 R101.1
NetH200_1: H200.1 R204.2 | length 21.5
  SIGNAL_1 w0.25: H200.1 6.15,36.05 21,36.05 21.952,37.002 R204.2
NetH200_2: H200.2 R203.2 | length 22.2
  SIGNAL_1 w0.25: H200.2 8.19,35.55 21.05,35.55 21.599,35.001 R203.2
NetH200_4: H200.4 R202.2 | length 24.7
  SIGNAL_1 w0.25: H200.4 12.72,35 20.45,35 22.449,33.001 R202.2
NetH200_5: H200.5 R207.2 | length 21.4
  SIGNAL_1 w0.25: H200.5 5.06,24.8 20.15,24.8 21.95,23 R207.2
NetH200_6: H200.6 R201.2 | length 13.8
  SIGNAL_1 w0.25: v1(22.7,31) R201.2
  SIGNAL_4 w0.25: H200.6 23.37,23.52 23.85,24 23.85,29.85 v1(22.7,31)
NetH200_7: H200.7 R200.2 | length 7.2
  SIGNAL_1 w0.25: v1@22.701,29.001 R200.2
  SIGNAL_4 w0.25: H200.7 20.417,26.06 21,26.643 21,28.5 21.5,29 v1(22.7,29)
NetH200_9: H200.9 R205.2 | length 9.7
  SIGNAL_1 w0.25: H200.9 20.35,29.81 20.35,26 21.35,25 R205.2
NetH200_10: H200.10 R206.2 | length 9.8
  SIGNAL_1 w0.25: H200.10 21.15,31.55 21.15,27.95 22.1,27 R206.2
NetH201_1: H201.1 R212.2 | length 21.8
  SIGNAL_1 w0.25: H201.1 6.15,22.35 20.15,22.35 21.799,20.701 R212.2
NetH201_2: H201.2 R211.2 | length 23.3
  SIGNAL_1 w0.25: H201.2 8.14,21.8 19.9,21.8 22.999,18.701 R211.2
NetH201_4: H201.4 R210.2 | length 26.6
  SIGNAL_1 w0.25: H201.4 12.67,21.25 19.7,21.25 22.25,18.7 22.25,17.25 22.799,16.701 R210.2
NetH201_5: H201.5 R215.2 | length 21.5
  SIGNAL_1 w0.25: H201.5 6.9,6.7 R215.2
NetH201_6: H201.6 R209.2 | length 10.8
  SIGNAL_1 w0.25: v1@22.701,14.7 R209.2
  SIGNAL_4 w0.25: H201.6 19.75,10.55 23.5,10.55 23.8,10.85 23.8,13.599 v1(22.7,14.699)
NetH201_7: H201.7 R208.2 | length 5.1
  SIGNAL_1 w0.25: v1(22.7,12.699) R208.2
  SIGNAL_4 w0.25: H201.7 22.361,12.36 v1(22.7,12.699)
NetH201_9: H201.9 R213.2 | length 12.3
  SIGNAL_1 w0.25: H201.9 20.45,16.01 20.45,9.6 21.35,8.7 R213.2
NetH201_10: H201.10 R214.2 | length 12.6
  SIGNAL_1 w0.25: H201.10 21.35,17.65 21.35,11.05 21.7,10.7 R214.2
NetR103_2: R103.2 S100.9 U101.20 | length 18.2
  SIGNAL_1 w0.25: S100.9 16.04,66.21 R103.2 16.05,65.25 16.3,65 18.9,65 20.7,66.8 20.7,69.7 23.275,72.275 U101.20
NetR104_2: R104.2 S100.10 U101.19 | length 16.6
  SIGNAL_1 w0.25: S100.10 16,68.75 R104.2 16.05,67.75 16.3,67.5 18.9,67.5 20,68.6 20,70 22.925,72.925 U101.19
NetR105_2: R105.2 S100.11 U101.18 | length 14.9
  SIGNAL_1 w0.25: S100.11 16.04,71.29 R105.2 16.05,70.35 16.3,70.1 19.15,70.1 22.625,73.575 U101.18
NetR106_2: R106.2 S100.12 U101.17 | length 14.1
  SIGNAL_1 w0.25: S100.12 16.02,73.83 R106.2 16.05,72.85 16.3,72.6 20.7,72.6 22.325,74.225 U101.17
NetR107_1: R107.1 S100.16 U101.1 | length 33.1
  SIGNAL_1 w0.25: S100.16 v1(14.8,83.99) 16.04,83.99 R107.1 ; U101.1 34.275,72.275 v1(34.3,72.3)
  SIGNAL_4 w0.25: v1(14.8,83.99) 13.7,82.89 13.7,80.8 14.8,79.7 20.4,79.7 28.2,71.9 32.5,71.9 32.9,72.3 v1(34.3,72.3)
NetR108_1: R108.1 S100.15 U101.2 | length 24.4
  SIGNAL_1 w0.25: S100.15 14.65,81.45 14.7,81.4 v1(14.8,81.4) R108.1 ; v1(30.7,72.9) 30.725,72.925 U101.2
  SIGNAL_4 w0.25: v1(14.8,81.4) 15.6,80.6 20.9,80.6 28.6,72.9 v1(30.7,72.9)
NetR109_1: R109.1 S100.14 U101.13 | length 14.8
  SIGNAL_1 w0.25: S100.14 16.04,78.91 R109.1 16.05,79.85 16.3,80.1 20.8,80.1 24.075,76.825 U101.13
NetR110_1: R110.1 S100.13 U101.14 | length 14.1
  SIGNAL_1 w0.25: S100.13 16.02,76.37 R110.1 16.05,77.35 16.3,77.6 22.4,77.6 23.825,76.175 U101.14
NetR111_1: R111.1 S100.1 S100.2 S100.3 S100.4 S100.5 S100.6 S100.7 S100.8 | length 46.1
  SIGNAL_1 w0.25: R111.1 3.45,66.21 S100.8 5.71,66.21 6,66.5 6,68.5 5.75,68.75 S100.7 2.45,68.75 2.2,69 2.2,71 2.5,71.3 S100.6@4.09,71.3 ; S100.4@4.09,76.38 4.08,76.39 2.49,76.39 2.19,76.09 2.19,74.09 2.44,73.84 4.09,73.84 5.74,73.84 5.99,73.59 5.99,71.59 5.7,71.3 S100.6@4.09,71.3 ; S100.6 S100.6@4.09,71.3 ; S100.4 5.71,76.37 6,76.66 6,78.66 5.75,78.91 S100.3 2.45,78.91 2.2,79.16 2.2,81.16 2.5,81.46 4.09,81.46 S100.2 5.71,81.45 6,81.74 6,83.74 5.75,83.99 S100.1
NetR112_2: R112.2 R113.1 S101.1 | length 5.4
  SIGNAL_1 w0.25: R113.1 R112.2 27.8,88.65 27.65,88.8 S101.1
NetR113_2: R113.2 U101.12 | length 9.6
  SIGNAL_1 w0.25: U101.12 24.225,77.475 23.7,78 23.7,81.6 25.7,83.6 R113.2
NetR114_1: R114.1 R115.2 S102.1 | length 5.4
  SIGNAL_1 w0.25: R114.1 R115.2 35.9,88.622 35.652,88.87 S102.1
NetR114_2: R114.2 U101.11 | length 13.9
  SIGNAL_1 w0.25: U101.11 25.3,81.4 27.4,83.5 33.3,83.5 33.8,84 R114.2
NetR200_1: R200.1 U202.13 | length 5
  SIGNAL_1 w0.25: R200.1 27.201,29.001 28.565,30.365 U202.13
NetR201_1: R201.1 U202.12 | length 4.7
  SIGNAL_1 w0.25: R201.1 27.6,31 28.235,31.635 U202.12
NetR202_1: R202.1 U202.11 | length 4.5
  SIGNAL_1 w0.25: R202.1 25.946,32.905 U202.11
NetR203_1: R203.1 U202.10 | length 4.8
  SIGNAL_1 w0.25: R203.1 25.851,35 27.4,35 28.225,34.175 U202.10
NetR204_1: R204.1 U202.9 | length 5.1
  SIGNAL_1 w0.25: R204.1 25.852,37 27,37 28.555,35.445 U202.9
NetR205_1: R205.1 U202.15 | length 5.6
  SIGNAL_1 w0.25: R205.1 26.5,25 29.325,27.825 U202.15
NetR206_1: R206.1 U202.14 | length 5.3
  SIGNAL_1 w0.25: R206.1 26.8,27 28.895,29.095 U202.14
NetR208_1: R208.1 U203.13 | length 5
  SIGNAL_1 w0.25: R208.1 27.201,12.701 28.565,14.065 U203.13
NetR209_1: R209.1 U203.12 | length 4.7
  SIGNAL_1 w0.25: R209.1@25.851,14.7 27.6,14.7 28.235,15.335 U203.12
NetR210_1: R210.1 U203.11 | length 4.5
  SIGNAL_1 w0.25: R210.1 25.946,16.605 U203.11
NetR211_1: R211.1 U203.10 | length 4.8
  SIGNAL_1 w0.25: R211.1 25.851,18.7 27.4,18.7 28.225,17.875 U203.10
NetR212_1: R212.1 U203.9 | length 5.1
  SIGNAL_1 w0.25: R212.1 25.852,20.7 27,20.7 28.555,19.145 U203.9
NetR213_1: R213.1 U203.15 | length 5.6
  SIGNAL_1 w0.25: R213.1 26.5,8.7 29.325,11.525 U203.15
NetR214_1: R214.1 U203.14 | length 5.3
  SIGNAL_1 w0.25: R214.1 26.8,10.7 28.895,12.795 U203.14
NetR216_2: R216.2 R225.1 S201.2 | length 4.3
  SIGNAL_1 w0.25: R216.2 44.6,33.35 R225.1 44.75,34.65 45.4,35.3 S201.2
NetR217_1: R217.1 U201.1 | length 38
  SIGNAL_1 w0.25: R217.1 v1(46.4,24.5) ; U201.1 66.725,10.675 v1(66.8,10.6)
  SIGNAL_4 w0.25: v1(46.4,24.5) 45.35,23.45 45.35,13.95 50.05,9.25 65.45,9.25 v1(66.8,10.6)
NetR217_2: R217.2 U202.7 X200.8 | length 16
  SIGNAL_1 w0.25: U202.7 37.375,34.175 38.1,33.45 38.1,30 38.95,29.15 38.95,24.75 39.21,24.49 X200.8 40.31,24.5 R217.2
NetR218_1: R218.1 U201.2 | length 30
  SIGNAL_1 w0.25: R218.1 v1(46.4,21.9) ; v1(63.6,11.3) 63.625,11.325 U201.2
  SIGNAL_4 w0.25: v1(46.4,21.9) 46.4,14.35 50.6,10.15 62.45,10.15 v1(63.6,11.3)
NetR218_2: R218.2 U202.1 X200.7 | length 11.5
  SIGNAL_1 w0.25: U202.1 37.125,26.555 v1(37.15,26.53) ; X200.7 40.35,21.9 R218.2
  SIGNAL_4 w0.25: v1(37.15,26.53) 37.15,22.8 38,21.95 X200.7
NetR219_1: R219.1 U201.13 | length 14.8
  SIGNAL_1 w0.25: R219.1 52.4,19.4 56.575,15.225 U201.13
NetR219_2: R219.2 U202.2 X200.6 | length 16.9
  SIGNAL_1 w0.25: U202.2 37.125,27.825 v1(37.15,27.8) ; X200.6 40.31,19.4 R219.2
  SIGNAL_4 w0.25: v1(37.15,27.8) 36.5,27.8 36.15,27.45 36.15,20.6 37.34,19.41 X200.6
NetR220_1: R220.1 U201.14 | length 14
  SIGNAL_1 w0.25: R220.1 54.1,16.9 56.425,14.575 U201.14
NetR220_2: R220.2 U202.6 X200.5 | length 22.1
  SIGNAL_1 w0.25: U202.6 36.995,32.905 37.3,32.6 37.3,29.5 38.1,28.7 38.1,17.9 39.13,16.87 X200.5 40.33,16.9 R220.2
NetR221_1: R221.1 U201.17 | length 13.7
  SIGNAL_1 w0.25: R221.1 50.6,14.3 52.275,12.625 U201.17
NetR221_2: R221.2 U203.7 X200.4 | length 9.9
  SIGNAL_1 w0.25: U203.7 36.875,17.875 38.1,16.65 38.1,14.8 38.57,14.33 X200.4 40.33,14.3 R221.2
NetR222_1: R222.1 U201.18 | length 13.2
  SIGNAL_1 w0.25: R222.1 51.9,11.7 52.175,11.975 U201.18
NetR222_2: R222.2 U203.1 X200.3 | length 8
  SIGNAL_1 w0.25: U203.1 37.125,10.255 v1(37.15,10.23) ; X200.3 40.39,11.7 R222.2
  SIGNAL_4 w0.25: v1(37.15,10.23) 38.74,10.23 X200.3
NetR223_1: R223.1 U201.19 | length 13.9
  SIGNAL_1 w0.25: R223.1 50.4,9.2 52.525,11.325 U201.19
NetR223_2: R223.2 U203.2 X200.2 | length 12.1
  SIGNAL_1 w0.25: U203.2 37.125,11.525 v1(37.15,11.5) ; X200.2 40.35,9.2 R223.2
  SIGNAL_4 w0.25: v1(37.15,11.5) 36.05,11.5 35.7,11.15 35.7,9.65 36.1,9.25 X200.2
NetR224_1: R224.1 U201.20 | length 14.7
  SIGNAL_1 w0.25: R224.1 48.9,6.7 52.875,10.675 U201.20
NetR224_2: R224.2 U203.6 X200.1 | length 16.2
  SIGNAL_1 w0.25: U203.6 36.945,16.605 37.3,16.25 37.3,14.45 38.2,13.55 38.2,7.31 38.8,6.71 X200.1 40.31,6.7 R224.2
NetR225_2: R225.2 U201.11 | length 22.7
  SIGNAL_1 w0.25: R225.2 46.65,28.15 52.6,22.2 52.6,20.1 56.175,16.525 U201.11
NetR226_1: R226.1 U201.7 | length 2.7
  SIGNAL_1 w0.25: U201.7 67.825,14.575 R226.1
NetR227_1: R227.1 U202.4 | length 7.3
  SIGNAL_1 w0.25: R227.1 33.4,29.3 34.465,30.365 U202.4
NetR228_1: R228.1 U202.3 | length 6.4
  SIGNAL_1 w0.25: R228.1 34.9,24.75 34.9,25.45 34.2,26.15 34.2,28.7 34.595,29.095 U202.3
NetR229_1: R229.1 U203.4 | length 7.3
  SIGNAL_1 w0.25: R229.1 33.4,13 34.465,14.065 U203.4
NetR230_1: R230.1 U203.3 | length 6.3
  SIGNAL_1 w0.25: R230.1 35.1,8.45 34.85,8.7 34.85,9.147 34.2,9.797 34.2,12.4 34.595,12.795 U203.3
NetU100_2: U100.2 U101.9 | length 37
  SIGNAL_1 w0.25: U101.9 67.675,77.475 68,77.8 67.98,77.82 U100.2
RF_RX: U200.16 W200.1 | length 11.6
  SIGNAL_1 w0.2: U200.16@73.447,37.69 84.99,37.69 W200.1
RF_TX: U100.5 W100.1 | length 12.6
  SIGNAL_1 w0.2: U100.5 85.618,87.768 W100.1
RX_DATA: U200.8 U201.12 | length 7
  SIGNAL_1 w0.25: U200.8@57.953,19.91 59.39,19.91 59.6,19.7 59.6,16.1 59.375,15.875 U201.12
pads on no net: S101. S102. S201. U200.1 U200.2 U200.3 U200.6 U200.7 U200.9 U200.10 U200.11 U200.12 U200.13 U200.14 U201.9

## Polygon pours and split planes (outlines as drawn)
GND_RX on SIGNAL_2 "02-GND_RX" (solid, remove dead copper, pour order 6): 0,0 100,0 100,50 0,50
GND_TX on SIGNAL_2 "02-GND_TX" (solid, remove dead copper, pour order 0): 0,50 100,50 100,100 0,100
3V3_RX on SIGNAL_3 "03-3V3_RX" (solid, remove dead copper, pour order 5): 0,0 100,0 100,50 0,50
3V3_TX on SIGNAL_3 "03-3V3_TX" (solid, remove dead copper, pour order 1): 0,50 100,50 100,100 0,100
GND_RX on SIGNAL_1 "01-GND_RX" (solid, remove dead copper, pour order 7): 0,0 100,0 100,50 0,50
GND_TX on SIGNAL_1 "01-GND_TX" (solid, remove dead copper, pour order 2): 0,50 100,50 100,100 0,100
GND_RX on SIGNAL_4 "04-GND_RX" (solid, remove dead copper, pour order 4): 0,0 100,0 100,50 0,50
GND_TX on SIGNAL_4 "04-GND_TX" (solid, remove dead copper, pour order 3): 0,50 100,50 100,100 0,100

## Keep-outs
Keep-Out Layer:
  lines w0.7: 0,50 100,50 ; 0,0 0,100 100,100 100,0 0,0

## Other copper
SIGNAL_1:
  pour cut-out: 99.1,3 ccw(c97,3) 97,5.1 ccw(c97,3) 94.9,3 ccw(c97,3) 97,0.9 ccw(c97,3)
  pour cut-out: 5.1,3 ccw(c3,3) 3,5.1 ccw(c3,3) 0.9,3 ccw(c3,3) 3,0.9 ccw(c3,3)
  pour cut-out: 5.1,47 ccw(c3,47) 3,49.1 ccw(c3,47) 0.9,47 ccw(c3,47) 3,44.9 ccw(c3,47)
  pour cut-out: 5.1,53 ccw(c3,53) 3,55.1 ccw(c3,53) 0.9,53 ccw(c3,53) 3,50.9 ccw(c3,53)
  pour cut-out: 99.1,47 ccw(c97,47) 97,49.1 ccw(c97,47) 94.9,47 ccw(c97,47) 97,44.9 ccw(c97,47)
  pour cut-out: 99.1,53 ccw(c97,53) 97,55.1 ccw(c97,53) 94.9,53 ccw(c97,53) 97,50.9 ccw(c97,53)
  pour cut-out: 99.1,97 ccw(c97,97) 97,99.1 ccw(c97,97) 94.9,97 ccw(c97,97) 97,94.9 ccw(c97,97)
  pour cut-out: 5.1,97 ccw(c3,97) 3,99.1 ccw(c3,97) 0.9,97 ccw(c3,97) 3,94.9 ccw(c3,97)
  text "Tx_433MHz V2.0" at 37.866,96.425 h2
  text "01/04" at 6.934,96.175 h2
  text "Rx_433MHz V2.0" at 37.656,46.5 h2
  text "LAYER TOP 01/02" at 37.5,-35.224 h2.5
  text "LAYER TOP 01/02" at 37.5,-35.224 h2.5
SIGNAL_2:
  text "02/04" at 6.934,96.175 h2
SIGNAL_3:
  text "03/04" at 6.934,96.175 h2
SIGNAL_4:
  text "04/04" at 16.264,96.175 h2
  text "LAYER BOTTOM 02/02" at 62.25,-35.224 h2.5

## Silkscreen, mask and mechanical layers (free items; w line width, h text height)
Top Overlay:
  drawing of 94 lines, arcs and shapes, not listed
  text "SILK SCREEN TOP" at 37.5,-35.224 h2.5
Bottom Overlay:
  text "SILK SCREEN BOTTOM" at 62.25,-35.224 h2.5
Top Paste:
  text "PASTEMASK TOP" at 57.75,-35.224 h2.5
Bottom Paste:
  text "PASTE MASK BOTTOM" at 36.5,-35.224 h2.5
DIELECTRIC_1:
  text "SOLDERMASK TOP" at 57.75,-35.224 h2.5
DIELECTRIC_9:
  text "SOLDERMASK BOTTOM" at 36.5,-35.224 h2.5
Top Assembly:
  text "U100" at 67.25,82.85 h1
  text "U101" at 27.35,75.05 h1
  text "W100" at 90.5,74.7 h1
  text "U102" at 22.3,57 h0.5
  text "X100" at 15.35,55.5 h1 r90
  text "U204" at 24.55,41.7 h1 r90
  text "X201" at 15.4,41.25 h1 r90
  text "U202" at 33.45,29.45 h1 r90
  text "U200" at 63.6,28.35 h1
  text "W200" at 90.4,24.65 h1
  text "H200" at 6.6,23.1 h1
  text "X200" at 40.75,13.85 h1 r90
  text "U203" at 33.55,13 h1 r90
  text "U201" at 60,12.95 h1
  text "H201" at 6.6,9.25 h1
Default User Layer:
  lines w0.025: 1,1 1,49 ; 1,1 85,1 ; 1,1 1,49 ; 1,1 85,1 ; 1,49 85,49 ; 1,49 85,49 ; 1,51 1,99 ; 1,51 85,51 ; 1,51 1,99 ; 1,51 85,51 ; 1,99 85,99 ; 1,99 85,99 ; 85,1 85,49 ; 85,1 85,49 ; 85,51 85,99 ; 85,51 85,99
ESD_Symbol:
  text "PANEL DRAWING" at 37.5,-35.224 h2.5
VSCORE_DETAIL:
  lines w0.1: 0,50 100,50
  text "V-CUTS" at 37.502,-35.224 h2.5
Panel Dimension:
  circle w0.2: c3,47 r1.1
  circle w0.2: c3,53 r1.1
  circle w0.2: c3,97 r1.1
  circle w0.2: c97,97 r1.1
  circle w0.2: c97,53 r1.1
  circle w0.2: c97,47 r1.1
  circle w0.2: c97,3 r1.1
  circle w0.2: c3,3 r1.1
  lines w0.2: 0,50 100,50 ; 0,0 0,100 100,100 100,0 0,0
Single Board Dimensions:
  circle w0.2: c3,3 r1.1
  circle w0.2: c97,3 r1.1
  circle w0.2: c97,47 r1.1
  circle w0.2: c97,53 r1.1
  circle w0.2: c97,97 r1.1
  circle w0.2: c3,97 r1.1
  circle w0.2: c3,53 r1.1
  circle w0.2: c3,47 r1.1
  lines w0.2: 0,50 100,50 ; 0,0 100,0 100,100 0,100 0,0
TitleBlock_Mirrored:
  drawing of 21 lines, arcs and shapes, not listed
  text "PCA NAME:" at 49,-25.989 h1
  text "PCA ID:" at 66,-25.989 h1
  text ".PCA_NAME" at 43.5,-27.28 h2.5
  text ".PCA_ID" at 62.25,-27.722 h2.5
  text "DRAWN BY:" at 66,-29.75 h1
  text ".PCB_AUTHOR" at 60.5,-31.474 h2.5
  text "www.sintecs.nl" at 76.9,-33.485 h1.5
  text "Amarilstraat 14" at 98.6,-33.485 h1.5
  text "LAYER:" at 66,-33.5 h1
  text "info@sintecs.nl" at 77.1,-35.017 h1.5
  text "7554 TV Hengelo (Ov)" at 98.6,-35.017 h1.5
  text "ASSEMBLY DRAWING BOTTOM" at 62.25,-35.224 h2.5
  text "Tel: +31 (0)74 2555 713" at 82.4,-36.717 h1.5
  text "DOC VER:" at 40,-37.239 h1
  text "PCB REV:" at 49,-37.239 h1
  text "PCB ID:" at 66,-37.239 h1
  text "DATE:" at 30.5,-37.25 h1
  text ".YEAR" at 91.401,-37.289 h1
  text "© SINTECS B.V." at 98.6,-37.289 h1
  text "No part of this design or any of its contents may be reproduced," at 98.6,-38.312 h1
  text ".Print_Date" at 27.25,-38.974 h2.5
  text ".PCB_DOC_VER" at 35,-38.974 h2.5
  text ".PCB_ID" at 62.25,-38.972 h2.5
  text ".PCB_REV" at 44,-39 h2.5
  text "copied, modified or adapted, without the prior written consent of Sintecs B.V." at 98.6,-39.322 h1
TittleBlock:
  drawing of 21 lines, arcs and shapes, not listed
  text "PCA ID:" at 34,-25.989 h1
  text "PCA NAME:" at 51,-25.989 h1
  text ".PCA_NAME" at 56.5,-27.28 h2.5
  text ".PCA_ID" at 37.75,-27.722 h2.5
  text "DRAWN BY:" at 34,-29.75 h1
  text ".PCB_AUTHOR" at 39.5,-31.474 h2.5
  text "Amarilstraat 14" at 1.4,-33.485 h1.5
  text "www.sintecs.nl" at 23.1,-33.485 h1.5
  text "LAYER:" at 34,-33.5 h1
  text "7554 TV Hengelo (Ov)" at 1.4,-35.017 h1.5
  text "info@sintecs.nl" at 22.9,-35.017 h1.5
  text "ASSEMBLY DRAWING TOP" at 37.5,-35.224 h2.5
  text "Tel: +31 (0)74 2555 713" at 17.6,-36.717 h1.5
  text "PCB ID:" at 34,-37.239 h1
  text "PCB REV:" at 51,-37.239 h1
  text "DOC VER:" at 60,-37.239 h1
  text "DATE:" at 69.5,-37.25 h1
  text "© SINTECS B.V." at 1.4,-37.289 h1
  text ".YEAR" at 8.599,-37.289 h1
  text "No part of this design or any of its contents may be reproduced," at 1.4,-38.312 h1
  text ".PCB_ID" at 37.75,-38.972 h2.5
  text ".PCB_DOC_VER" at 65,-38.974 h2.5
  text ".Print_Date" at 72.75,-38.974 h2.5
  text ".PCB_REV" at 56,-39 h2.5
  text "copied, modified or adapted, without the prior written consent of Sintecs B.V." at 1.4,-39.322 h1
Fab Notes:
  text "MANUFACTURING INFORMATION" at 37.5,-35.224 h2.5
Board:
  text "PANEL DIMENSIONS" at 37.5,-35.224 h2.5
Dimensions:
  text "BOARD DIMENSIONS" at 37.5,-35.224 h2.5
Bottom 3D Body:
  text "3D BODIES BOTTOM" at 62.25,-35.224 h2.5
Top 3D Body:
  text "3D BODIES TOP" at 37.5,-35.224 h2.5
Board Shape:
  text "BOARD SHAPE" at 37.5,-35.224 h2.5

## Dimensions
0,100 to 1.9,97 on Single Board Dimensions
1.9,53 to 0,50 on Single Board Dimensions
0,0 to 3,1.9 on Single Board Dimensions
0,0 to 100,0 on Single Board Dimensions
97,1.9 to 100,0 on Single Board Dimensions
0,0 to 1.9,3 on Single Board Dimensions
0,0 to 0,50 on Single Board Dimensions
0,0 to 0,100 on Single Board Dimensions
0,50 to 1.9,47 on Single Board Dimensions
3,3 to 5.6,4.3 on Single Board Dimensions
0,0 to 0,100 on Panel Dimension
0,0 to 100,0 on Panel Dimension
